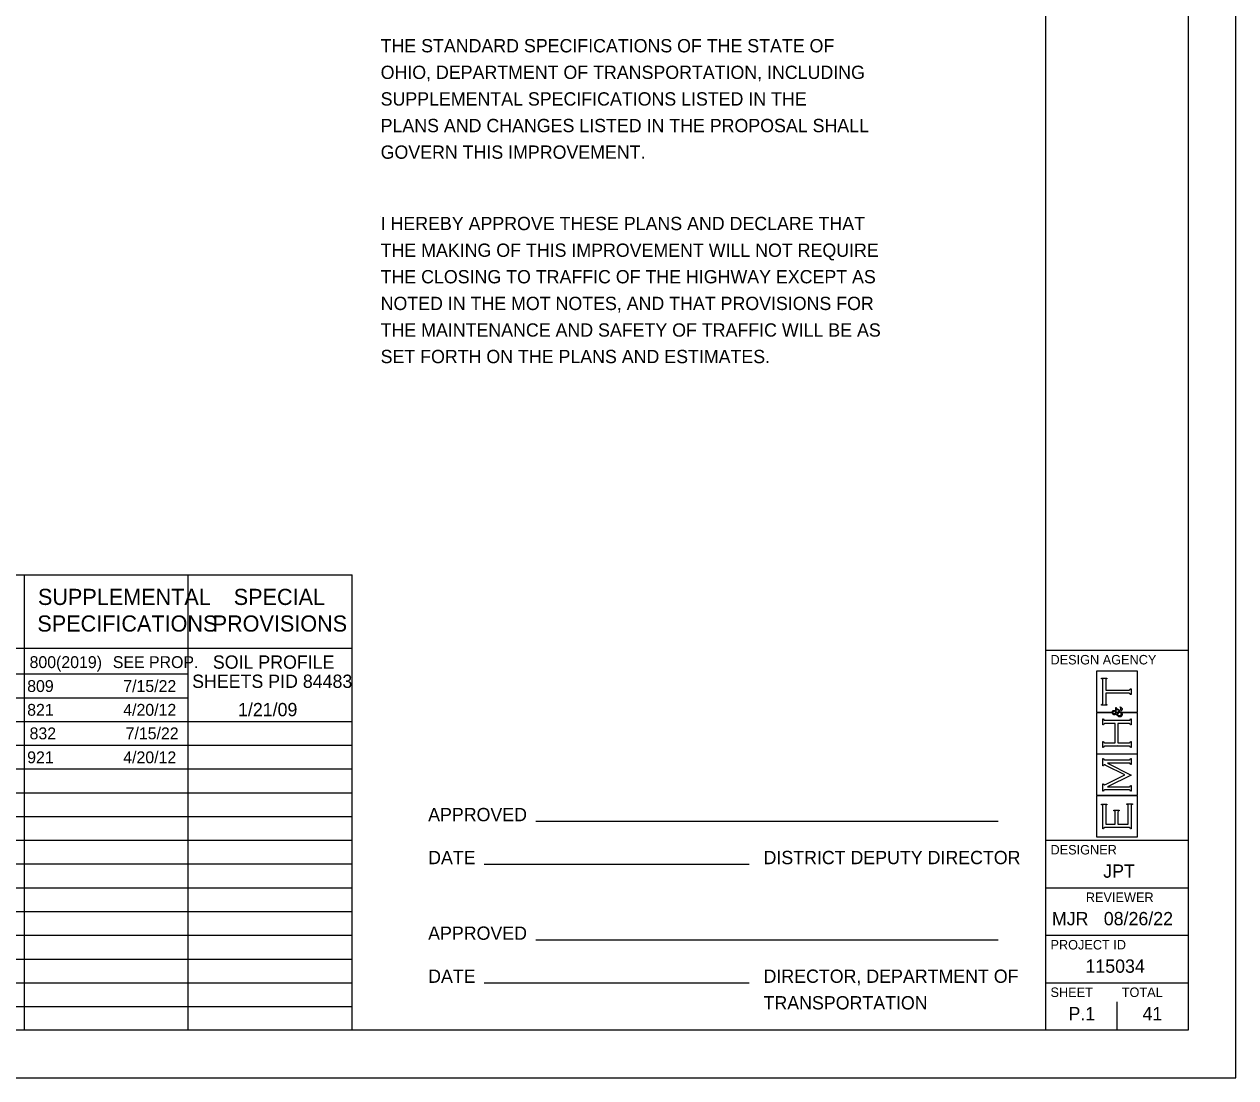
# Model space of a CAD drawing. Extents: x 0 to 34, y 0 to 22.
# Drawn here: x 21.25 to 34, y 0 to 11.09 of the extents above; entities that cross this region are included whole.
import ezdxf

# ---------------------------------------------------------------- set-up
doc = ezdxf.new("R2010")
doc.units = 0
for name, color, linetype in [('Default', 7, 'Continuous'), ('SH_Border', 7, 'Continuous'), ('SH_Cut_Line', 7, 'Continuous'), ('SH_Data', 7, 'Continuous'), ('SH_Text', 7, 'Continuous')]:
    doc.layers.add(name, color=color, linetype=linetype)

msp = doc.modelspace()

# ---------------------------------------------------------------- linework, layer by layer
at = {"layer": 'SH_Border'}
for p, q in [((32, 0.5), (32, 21.5)), ((32, 4.5), (33.5, 4.5)), ((32, 2.5), (33.5, 2.5)), ((32, 2), (33.5, 2)), ((32, 1.5), (33.5, 1.5)), ((32, 1), (33.5, 1))]:
    msp.add_line(p, q, dxfattribs=at)
msp.add_lwpolyline([(1.5, 21.5), (33.5, 21.5), (33.5, 0.5), (1.5, 0.5)], close=True, dxfattribs=at)
at = {"layer": 'SH_Cut_Line'}
msp.add_lwpolyline([(0, 0), (34, 0), (34, 22), (0, 22)], close=True, dxfattribs=at)
at = {"layer": 'SH_Data'}
for p, q in [((25, 9.06), (25, 9.06)), ((11.25, 5.292), (24.7, 5.292)), ((21.25, 0.5), (21.25, 5.292)), ((22.975, 0.5), (22.975, 5.292)), ((24.7, 0.5), (24.7, 5.292)), ((11.25, 4.521), (24.7, 4.521)), ((11.25, 4.25), (22.975, 4.25)), ((32.966, 4.28), (32.534, 4.28)), ((32.534, 4.28), (32.534, 3.848)), ((32.966, 3.848), (32.966, 4.28)), ((32.588, 4.199), (32.588, 4.206)), ((32.588, 4.206), (32.644, 4.206)), ((32.594, 4.198), (32.588, 4.199)), ((32.598, 4.196), (32.594, 4.198)), ((32.599, 4.194), (32.598, 4.196)), ((32.601, 4.191), (32.599, 4.194)), ((32.602, 4.187), (32.601, 4.191)), ((32.602, 4.181), (32.602, 4.187)), ((32.602, 3.947), (32.602, 4.181)), ((32.632, 4.191), (32.631, 4.187)), ((32.631, 4.187), (32.631, 4.181)), ((32.631, 4.181), (32.631, 4.081)), ((32.631, 4.081), (32.872, 4.081)), ((32.633, 4.194), (32.632, 4.191)), ((32.635, 4.196), (32.633, 4.194)), ((32.639, 4.198), (32.635, 4.196)), ((32.644, 4.199), (32.639, 4.198)), ((32.644, 4.206), (32.644, 4.199)), ((32.872, 4.081), (32.878, 4.081)), ((32.878, 4.081), (32.882, 4.082)), ((32.882, 4.082), (32.885, 4.084)), ((32.885, 4.084), (32.887, 4.085)), ((32.887, 4.085), (32.889, 4.089)), ((32.889, 4.089), (32.891, 4.095)), ((32.891, 4.095), (32.898, 4.095)), ((32.898, 4.095), (32.898, 4.033)), ((11.25, 4), (22.975, 4)), ((32.872, 4.047), (32.631, 4.047)), ((32.631, 4.047), (32.631, 3.947)), ((32.878, 4.047), (32.872, 4.047)), ((32.883, 4.046), (32.878, 4.047)), ((32.885, 4.044), (32.883, 4.046)), ((32.888, 4.042), (32.885, 4.044)), ((32.889, 4.039), (32.888, 4.042)), ((32.891, 4.033), (32.889, 4.039)), ((32.898, 4.033), (32.891, 4.033)), ((32.534, 3.848), (32.693, 3.848)), ((32.693, 3.842), (32.534, 3.842)), ((32.534, 3.842), (32.534, 3.41)), ((32.588, 3.928), (32.594, 3.93)), ((32.588, 3.921), (32.588, 3.928)), ((32.644, 3.921), (32.588, 3.921)), ((32.594, 3.93), (32.598, 3.932)), ((32.598, 3.932), (32.599, 3.934)), ((32.599, 3.934), (32.601, 3.937)), ((32.601, 3.937), (32.602, 3.941)), ((32.602, 3.941), (32.602, 3.947)), ((32.631, 3.947), (32.631, 3.941)), ((32.631, 3.941), (32.632, 3.937)), ((32.632, 3.937), (32.633, 3.934)), ((32.633, 3.934), (32.635, 3.932)), ((32.635, 3.932), (32.639, 3.93)), ((32.639, 3.93), (32.644, 3.928)), ((32.644, 3.928), (32.644, 3.921)), ((32.693, 3.848), (32.693, 3.842)), ((32.701, 3.852), (32.703, 3.857)), ((32.701, 3.846), (32.701, 3.852)), ((32.701, 3.84), (32.701, 3.846)), ((32.703, 3.835), (32.701, 3.84)), ((32.703, 3.857), (32.706, 3.861)), ((32.706, 3.83), (32.703, 3.835)), ((32.706, 3.861), (32.71, 3.864)), ((32.707, 3.852), (32.706, 3.849)), ((32.706, 3.849), (32.706, 3.846)), ((32.706, 3.846), (32.706, 3.842)), ((32.706, 3.842), (32.708, 3.839)), ((32.71, 3.824), (32.706, 3.83)), ((32.71, 3.854), (32.707, 3.852)), ((32.708, 3.839), (32.711, 3.837)), ((32.71, 3.864), (32.714, 3.866)), ((32.712, 3.856), (32.71, 3.854)), ((32.711, 3.837), (32.714, 3.835)), ((32.715, 3.857), (32.712, 3.856)), ((32.714, 3.866), (32.719, 3.866)), ((32.714, 3.835), (32.716, 3.834)), ((32.718, 3.857), (32.715, 3.857)), ((32.716, 3.834), (32.719, 3.834)), ((32.723, 3.857), (32.718, 3.857)), ((32.719, 3.866), (32.724, 3.866)), ((32.719, 3.834), (32.722, 3.834)), ((32.722, 3.834), (32.724, 3.834)), ((32.727, 3.856), (32.723, 3.857)), ((32.724, 3.866), (32.728, 3.864)), ((32.724, 3.834), (32.727, 3.835)), ((32.73, 3.853), (32.727, 3.856)), ((32.727, 3.835), (32.73, 3.836)), ((32.728, 3.864), (32.732, 3.861)), ((32.734, 3.85), (32.73, 3.853)), ((32.73, 3.836), (32.734, 3.837)), ((32.732, 3.861), (32.736, 3.857)), ((32.737, 3.845), (32.734, 3.85)), ((32.734, 3.837), (32.74, 3.839)), ((32.736, 3.857), (32.74, 3.851)), ((32.74, 3.839), (32.737, 3.845)), ((32.738, 3.867), (32.738, 3.898)), ((32.738, 3.898), (32.741, 3.898)), ((32.741, 3.867), (32.738, 3.867)), ((32.74, 3.851), (32.745, 3.842)), ((32.741, 3.898), (32.741, 3.894)), ((32.741, 3.894), (32.742, 3.891)), ((32.742, 3.871), (32.741, 3.869)), ((32.741, 3.869), (32.741, 3.867)), ((32.746, 3.827), (32.741, 3.825)), ((32.742, 3.891), (32.744, 3.889)), ((32.743, 3.872), (32.742, 3.871)), ((32.745, 3.873), (32.743, 3.872)), ((32.744, 3.889), (32.745, 3.887)), ((32.745, 3.887), (32.75, 3.883)), ((32.747, 3.874), (32.745, 3.873)), ((32.745, 3.842), (32.755, 3.848)), ((32.753, 3.815), (32.746, 3.827)), ((32.749, 3.874), (32.747, 3.874)), ((32.756, 3.874), (32.749, 3.874)), ((32.75, 3.883), (32.757, 3.879)), ((32.757, 3.832), (32.751, 3.829)), ((32.751, 3.829), (32.755, 3.824)), ((32.755, 3.848), (32.765, 3.855)), ((32.764, 3.87), (32.756, 3.874)), ((32.757, 3.879), (32.765, 3.875)), ((32.762, 3.835), (32.757, 3.832)), ((32.766, 3.838), (32.762, 3.835)), ((32.775, 3.861), (32.764, 3.87)), ((32.765, 3.875), (32.772, 3.87)), ((32.765, 3.855), (32.775, 3.861)), ((32.77, 3.84), (32.766, 3.838)), ((32.776, 3.845), (32.77, 3.84)), ((32.772, 3.87), (32.779, 3.865)), ((32.785, 3.851), (32.776, 3.845)), ((32.779, 3.865), (32.784, 3.869)), ((32.781, 3.9), (32.783, 3.902)), ((32.785, 3.899), (32.781, 3.9)), ((32.783, 3.902), (32.79, 3.901)), ((32.784, 3.869), (32.787, 3.873)), ((32.788, 3.897), (32.785, 3.899)), ((32.789, 3.846), (32.785, 3.851)), ((32.787, 3.873), (32.789, 3.876)), ((32.789, 3.895), (32.788, 3.897)), ((32.791, 3.892), (32.789, 3.895)), ((32.789, 3.876), (32.791, 3.88)), ((32.794, 3.859), (32.789, 3.855)), ((32.789, 3.855), (32.795, 3.849)), ((32.792, 3.842), (32.789, 3.846)), ((32.79, 3.901), (32.795, 3.898)), ((32.792, 3.89), (32.791, 3.892)), ((32.791, 3.88), (32.792, 3.883)), ((32.792, 3.886), (32.792, 3.89)), ((32.792, 3.883), (32.792, 3.886)), ((32.793, 3.839), (32.792, 3.842)), ((32.794, 3.837), (32.793, 3.839)), ((32.798, 3.864), (32.794, 3.859)), ((32.795, 3.834), (32.794, 3.837)), ((32.795, 3.898), (32.799, 3.894)), ((32.795, 3.849), (32.798, 3.843)), ((32.795, 3.831), (32.795, 3.834)), ((32.795, 3.825), (32.795, 3.831)), ((32.8, 3.868), (32.798, 3.864)), ((32.798, 3.843), (32.8, 3.839)), ((32.799, 3.894), (32.802, 3.89)), ((32.802, 3.872), (32.8, 3.868)), ((32.8, 3.839), (32.802, 3.834)), ((32.802, 3.89), (32.803, 3.885)), ((32.803, 3.876), (32.802, 3.872)), ((32.802, 3.834), (32.803, 3.829)), ((32.803, 3.885), (32.803, 3.88)), ((32.803, 3.88), (32.803, 3.876)), ((32.807, 3.842), (32.803, 3.848)), ((32.803, 3.848), (32.966, 3.848)), ((32.803, 3.829), (32.803, 3.823)), ((32.966, 3.842), (32.807, 3.842)), ((32.966, 3.41), (32.966, 3.842)), ((11.25, 3.75), (24.7, 3.75)), ((32.602, 3.714), (32.602, 3.776)), ((32.602, 3.776), (32.609, 3.776)), ((32.609, 3.714), (32.602, 3.714)), ((32.609, 3.776), (32.611, 3.77)), ((32.61, 3.72), (32.609, 3.714)), ((32.612, 3.723), (32.61, 3.72)), ((32.611, 3.77), (32.612, 3.766)), ((32.612, 3.766), (32.615, 3.765)), ((32.615, 3.725), (32.612, 3.723)), ((32.615, 3.765), (32.617, 3.763)), ((32.617, 3.727), (32.615, 3.725)), ((32.617, 3.763), (32.622, 3.762)), ((32.622, 3.728), (32.617, 3.727)), ((32.622, 3.762), (32.628, 3.762)), ((32.628, 3.728), (32.622, 3.728)), ((32.628, 3.762), (32.872, 3.762)), ((32.732, 3.728), (32.628, 3.728)), ((32.717, 3.821), (32.71, 3.824)), ((32.725, 3.821), (32.717, 3.821)), ((32.728, 3.821), (32.725, 3.821)), ((32.731, 3.822), (32.728, 3.821)), ((32.734, 3.822), (32.731, 3.822)), ((32.732, 3.525), (32.732, 3.728)), ((32.737, 3.823), (32.734, 3.822)), ((32.741, 3.825), (32.737, 3.823)), ((32.759, 3.808), (32.753, 3.815)), ((32.755, 3.824), (32.758, 3.819)), ((32.758, 3.819), (32.762, 3.817)), ((32.765, 3.803), (32.759, 3.808)), ((32.872, 3.728), (32.76, 3.728)), ((32.76, 3.728), (32.76, 3.525)), ((32.762, 3.817), (32.766, 3.814)), ((32.77, 3.799), (32.765, 3.803)), ((32.766, 3.814), (32.771, 3.812)), ((32.776, 3.797), (32.77, 3.799)), ((32.771, 3.812), (32.775, 3.812)), ((32.775, 3.812), (32.78, 3.812)), ((32.782, 3.797), (32.776, 3.797)), ((32.78, 3.812), (32.785, 3.814)), ((32.788, 3.797), (32.782, 3.797)), ((32.785, 3.814), (32.789, 3.817)), ((32.793, 3.8), (32.788, 3.797)), ((32.789, 3.817), (32.793, 3.821)), ((32.793, 3.821), (32.795, 3.825)), ((32.797, 3.804), (32.793, 3.8)), ((32.801, 3.809), (32.797, 3.804)), ((32.803, 3.815), (32.801, 3.809)), ((32.803, 3.823), (32.803, 3.815)), ((32.872, 3.762), (32.878, 3.762)), ((32.878, 3.728), (32.872, 3.728)), ((32.878, 3.762), (32.882, 3.763)), ((32.883, 3.727), (32.878, 3.728)), ((32.882, 3.763), (32.885, 3.765)), ((32.885, 3.725), (32.883, 3.727)), ((32.885, 3.765), (32.887, 3.766)), ((32.888, 3.723), (32.885, 3.725)), ((32.887, 3.766), (32.889, 3.77)), ((32.889, 3.72), (32.888, 3.723)), ((32.889, 3.77), (32.891, 3.776)), ((32.891, 3.714), (32.889, 3.72)), ((32.891, 3.776), (32.898, 3.776)), ((32.898, 3.714), (32.891, 3.714)), ((32.898, 3.776), (32.898, 3.714)), ((11.25, 3.5), (24.7, 3.5)), ((32.602, 3.477), (32.602, 3.538)), ((32.602, 3.538), (32.609, 3.538)), ((32.609, 3.477), (32.602, 3.477)), ((32.609, 3.538), (32.611, 3.533)), ((32.61, 3.482), (32.609, 3.477)), ((32.612, 3.486), (32.61, 3.482)), ((32.611, 3.533), (32.612, 3.529)), ((32.612, 3.529), (32.615, 3.527)), ((32.615, 3.488), (32.612, 3.486)), ((32.615, 3.527), (32.617, 3.526)), ((32.617, 3.49), (32.615, 3.488)), ((32.617, 3.526), (32.622, 3.525)), ((32.622, 3.491), (32.617, 3.49)), ((32.622, 3.525), (32.628, 3.525)), ((32.628, 3.491), (32.622, 3.491)), ((32.628, 3.525), (32.732, 3.525)), ((32.872, 3.491), (32.628, 3.491)), ((32.75, 3.5), (32.75, 3.5)), ((32.76, 3.525), (32.872, 3.525)), ((32.872, 3.525), (32.878, 3.525)), ((32.878, 3.491), (32.872, 3.491)), ((32.878, 3.525), (32.883, 3.525)), ((32.883, 3.49), (32.878, 3.491)), ((32.883, 3.525), (32.885, 3.527)), ((32.885, 3.488), (32.883, 3.49)), ((32.885, 3.527), (32.888, 3.529)), ((32.887, 3.486), (32.885, 3.488)), ((32.888, 3.529), (32.889, 3.533)), ((32.889, 3.482), (32.887, 3.486)), ((32.889, 3.533), (32.891, 3.538)), ((32.891, 3.477), (32.889, 3.482)), ((32.891, 3.538), (32.898, 3.538)), ((32.898, 3.477), (32.891, 3.477)), ((32.898, 3.538), (32.898, 3.477)), ((32.534, 3.41), (32.966, 3.41)), ((32.966, 3.405), (32.534, 3.405)), ((32.534, 3.405), (32.534, 2.973)), ((32.602, 3.283), (32.602, 3.36)), ((32.602, 3.36), (32.609, 3.36)), ((32.609, 3.36), (32.611, 3.354)), ((32.611, 3.354), (32.612, 3.351)), ((32.612, 3.351), (32.615, 3.349)), ((32.615, 3.349), (32.617, 3.347)), ((32.617, 3.347), (32.622, 3.346)), ((32.622, 3.346), (32.628, 3.346)), ((32.628, 3.346), (32.872, 3.346)), ((32.872, 3.346), (32.878, 3.346)), ((32.878, 3.346), (32.882, 3.347)), ((32.882, 3.347), (32.885, 3.349)), ((32.885, 3.349), (32.887, 3.351)), ((32.887, 3.351), (32.889, 3.354)), ((32.889, 3.354), (32.891, 3.36)), ((32.891, 3.36), (32.898, 3.36)), ((32.898, 3.36), (32.898, 3.298)), ((32.966, 2.973), (32.966, 3.405)), ((11.25, 3.25), (24.7, 3.25)), ((32.609, 3.283), (32.602, 3.283)), ((32.612, 3.29), (32.609, 3.283)), ((32.615, 3.293), (32.612, 3.29)), ((32.618, 3.293), (32.615, 3.293)), ((32.621, 3.293), (32.618, 3.293)), ((32.626, 3.292), (32.621, 3.293)), ((32.633, 3.288), (32.626, 3.292)), ((32.831, 3.189), (32.633, 3.288)), ((32.635, 3.09), (32.831, 3.189)), ((32.872, 3.312), (32.649, 3.312)), ((32.649, 3.312), (32.898, 3.186)), ((32.878, 3.312), (32.872, 3.312)), ((32.883, 3.311), (32.878, 3.312)), ((32.885, 3.31), (32.883, 3.311)), ((32.887, 3.308), (32.885, 3.31)), ((32.889, 3.304), (32.887, 3.308)), ((32.891, 3.298), (32.889, 3.304)), ((32.898, 3.298), (32.891, 3.298)), ((32.602, 3.017), (32.602, 3.094)), ((32.602, 3.094), (32.609, 3.094)), ((32.609, 3.094), (32.612, 3.087)), ((32.612, 3.087), (32.615, 3.083)), ((32.615, 3.083), (32.618, 3.083)), ((32.618, 3.083), (32.62, 3.083)), ((32.62, 3.083), (32.625, 3.086)), ((32.625, 3.086), (32.635, 3.09)), ((32.898, 3.186), (32.649, 3.062)), ((32.649, 3.062), (32.872, 3.062)), ((32.872, 3.062), (32.878, 3.062)), ((32.878, 3.062), (32.882, 3.063)), ((32.882, 3.063), (32.885, 3.065)), ((32.885, 3.065), (32.887, 3.067)), ((32.887, 3.067), (32.889, 3.07)), ((32.889, 3.07), (32.891, 3.076)), ((32.891, 3.076), (32.898, 3.076)), ((32.898, 3.076), (32.898, 3.017)), ((11.25, 3), (24.7, 3)), ((32.534, 2.973), (32.966, 2.973)), ((32.966, 2.967), (32.534, 2.967)), ((32.534, 2.967), (32.534, 2.535)), ((32.609, 3.017), (32.602, 3.017)), ((32.61, 3.023), (32.609, 3.017)), ((32.612, 3.026), (32.61, 3.023)), ((32.615, 3.028), (32.612, 3.026)), ((32.617, 3.03), (32.615, 3.028)), ((32.622, 3.031), (32.617, 3.03)), ((32.628, 3.031), (32.622, 3.031)), ((32.872, 3.031), (32.628, 3.031)), ((32.878, 3.031), (32.872, 3.031)), ((32.883, 3.03), (32.878, 3.031)), ((32.885, 3.028), (32.883, 3.03)), ((32.887, 3.026), (32.885, 3.028)), ((32.889, 3.023), (32.887, 3.026)), ((32.891, 3.017), (32.889, 3.023)), ((32.898, 3.017), (32.891, 3.017)), ((32.966, 2.535), (32.966, 2.967)), ((32.588, 2.874), (32.588, 2.881)), ((32.588, 2.881), (32.644, 2.881)), ((32.594, 2.873), (32.588, 2.874)), ((32.598, 2.871), (32.594, 2.873)), ((32.599, 2.868), (32.598, 2.871)), ((32.601, 2.866), (32.599, 2.868)), ((32.602, 2.862), (32.601, 2.866)), ((32.602, 2.856), (32.602, 2.862)), ((32.602, 2.621), (32.602, 2.856)), ((32.632, 2.866), (32.631, 2.862)), ((32.631, 2.862), (32.631, 2.856)), ((32.631, 2.856), (32.631, 2.669)), ((32.633, 2.868), (32.632, 2.866)), ((32.635, 2.871), (32.633, 2.868)), ((32.639, 2.873), (32.635, 2.871)), ((32.644, 2.874), (32.639, 2.873)), ((32.644, 2.881), (32.644, 2.874)), ((32.718, 2.81), (32.718, 2.816)), ((32.718, 2.816), (32.774, 2.816)), ((32.723, 2.808), (32.718, 2.81)), ((32.727, 2.806), (32.723, 2.808)), ((32.729, 2.804), (32.727, 2.806)), ((32.765, 2.806), (32.763, 2.804)), ((32.768, 2.808), (32.765, 2.806)), ((32.774, 2.81), (32.768, 2.808)), ((32.774, 2.816), (32.774, 2.81)), ((32.855, 2.877), (32.855, 2.884)), ((32.855, 2.884), (32.912, 2.884)), ((32.861, 2.876), (32.855, 2.877)), ((32.865, 2.874), (32.861, 2.876)), ((32.867, 2.872), (32.865, 2.874)), ((32.868, 2.869), (32.867, 2.872)), ((32.869, 2.865), (32.868, 2.869)), ((32.869, 2.859), (32.869, 2.865)), ((32.869, 2.669), (32.869, 2.859)), ((32.899, 2.869), (32.898, 2.865)), ((32.898, 2.865), (32.898, 2.858)), ((32.898, 2.858), (32.898, 2.621)), ((32.901, 2.871), (32.899, 2.869)), ((32.903, 2.874), (32.901, 2.871)), ((32.906, 2.876), (32.903, 2.874)), ((32.912, 2.877), (32.906, 2.876)), ((32.912, 2.884), (32.912, 2.877)), ((11.25, 2.75), (24.7, 2.75)), ((26.635, 2.7), (31.5, 2.7)), ((32.731, 2.801), (32.729, 2.804)), ((32.732, 2.797), (32.731, 2.801)), ((32.732, 2.791), (32.732, 2.797)), ((32.732, 2.669), (32.732, 2.791)), ((32.761, 2.801), (32.76, 2.797)), ((32.76, 2.797), (32.76, 2.791)), ((32.76, 2.791), (32.76, 2.669)), ((32.763, 2.804), (32.761, 2.801)), ((32.609, 2.621), (32.602, 2.621)), ((32.611, 2.626), (32.609, 2.621)), ((32.612, 2.63), (32.611, 2.626)), ((32.615, 2.632), (32.612, 2.63)), ((32.617, 2.634), (32.615, 2.632)), ((32.622, 2.635), (32.617, 2.634)), ((32.628, 2.635), (32.622, 2.635)), ((32.872, 2.635), (32.628, 2.635)), ((32.631, 2.669), (32.732, 2.669)), ((32.76, 2.669), (32.869, 2.669)), ((32.878, 2.635), (32.872, 2.635)), ((32.883, 2.634), (32.878, 2.635)), ((32.885, 2.632), (32.883, 2.634)), ((32.887, 2.63), (32.885, 2.632)), ((32.889, 2.627), (32.887, 2.63)), ((32.891, 2.621), (32.889, 2.627)), ((32.898, 2.621), (32.891, 2.621)), ((11.25, 2.5), (24.7, 2.5)), ((32.534, 2.535), (32.966, 2.535)), ((11.25, 2.25), (24.7, 2.25)), ((26.091, 2.248), (28.878, 2.248)), ((11.25, 2), (24.7, 2)), ((11.25, 1.75), (24.7, 1.75)), ((11.25, 1.5), (24.7, 1.5)), ((26.635, 1.452), (31.5, 1.452)), ((11.25, 1.25), (24.7, 1.25)), ((11.25, 1), (24.7, 1)), ((26.091, 0.999), (28.878, 0.999)), ((32.75, 0.5), (32.75, 0.8)), ((11.25, 0.75), (24.7, 0.75)), ((32.375, 0.675), (32.375, 0.675))]:
    msp.add_line(p, q, dxfattribs=at)

# ---------------------------------------------------------------- texts
at = {"layer": 'Default'}
for s, height, p in [('I HEREBY APPROVE THESE PLANS AND DECLARE THAT', 0.14, (25, 8.921)), ('THE MAKING OF THIS IMPROVEMENT WILL NOT REQUIRE', 0.14, (25, 8.64)), ('THE CLOSING TO TRAFFIC OF THE HIGHWAY EXCEPT AS ', 0.14, (25, 8.361)), ('NOTED IN THE MOT NOTES, AND THAT PROVISIONS FOR ', 0.14, (25, 8.08)), ('THE MAINTENANCE AND SAFETY OF TRAFFIC WILL BE AS ', 0.14, (25, 7.8)), ('SET FORTH ON THE PLANS AND ESTIMATES.', 0.14, (25, 7.521)), ('800(2019)', 0.125, (21.305, 4.312)), ('SEE PROP.', 0.125, (22.181, 4.312)), ('809', 0.125, (21.28, 4.06)), ('7/15/22', 0.125, (22.291, 4.06)), ('821', 0.125, (21.28, 3.81)), ('4/20/12', 0.125, (22.291, 3.81)), ('832', 0.125, (21.305, 3.562)), ('7/15/22', 0.125, (22.316, 3.562)), ('921', 0.125, (21.28, 3.31)), ('4/20/12', 0.125, (22.291, 3.31))]:
    msp.add_text(s, height=height, dxfattribs=at).set_placement(p)
at = {"layer": 'SH_Data'}
for s, height, p in [('DESIGN AGENCY', 0.1, (32.05, 4.35)), ('DESIGNER', 0.1, (32.05, 2.35)), ('JPT', 0.14, (32.605, 2.105)), ('REVIEWER', 0.1, (32.422, 1.85)), ('MJR', 0.14, (32.065, 1.605)), ('08/26/22', 0.14, (32.611, 1.605)), ('PROJECT ID', 0.1, (32.05, 1.35)), ('115034', 0.14, (32.418, 1.105)), ('SHEET', 0.1, (32.05, 0.85)), ('TOTAL', 0.1, (32.8, 0.85)), ('P.1', 0.14, (32.24, 0.605)), ('41', 0.14, (33.019, 0.605))]:
    msp.add_text(s, height=height, dxfattribs=at).set_placement(p)
at = {"layer": 'SH_Text'}
for s, height, p in [('THE STANDARD SPECIFICATIONS OF THE STATE OF', 0.14, (25, 10.792)), ('OHIO, DEPARTMENT OF TRANSPORTATION, INCLUDING', 0.14, (25, 10.512)), ('SUPPLEMENTAL SPECIFICATIONS LISTED IN THE', 0.14, (25, 10.232)), ('PLANS AND CHANGES LISTED IN THE PROPOSAL SHALL', 0.14, (25, 9.952)), ('GOVERN THIS IMPROVEMENT.', 0.14, (25, 9.672)), ('SUPPLEMENTAL', 0.17, (21.393, 4.976)), ('SPECIAL', 0.17, (23.454, 4.976)), ('SPECIFICATIONS', 0.17, (21.387, 4.696)), ('PROVISIONS', 0.17, (23.232, 4.696)), ('SOIL PROFILE ', 0.14, (23.234, 4.305)), ('SHEETS PID 84483', 0.14, (23.016, 4.103)), ('1/21/09', 0.14, (23.499, 3.805)), ('APPROVED', 0.14, (25.5, 2.7)), ('DATE', 0.14, (25.5, 2.248)), ('DISTRICT DEPUTY DIRECTOR', 0.14, (29.03, 2.248)), ('APPROVED', 0.14, (25.5, 1.452)), ('DATE', 0.14, (25.5, 0.999)), ('DIRECTOR, DEPARTMENT OF', 0.14, (29.03, 0.999)), ('TRANSPORTATION', 0.14, (29.03, 0.719))]:
    msp.add_text(s, height=height, dxfattribs=at).set_placement(p)

doc.saveas('drawing.dxf')
